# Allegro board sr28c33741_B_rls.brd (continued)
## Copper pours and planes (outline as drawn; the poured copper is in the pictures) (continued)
GND on TOP (solid shape): 53.28,38.06 48.51,38.06 48.25,38.01 48.02,37.86 45.55,35.39 45.4,35.16 45.35,34.9 45.35,32.22 45.4,31.96 45.55,31.73 48.07,29.21 48.3,29.06 48.56,29.01 51.29,29.01 51.78,28.91 52.21,28.62 58.19,22.64 58.42,22.49 58.68,22.44 60.44,22.44 60.94,22.64 61.14,23.14 61.14,28.14 61.09,28.41 60.94,28.64 59.27,30.3 58.99,30.72 58.89,31.22 58.89,33.86 58.8,34.07 58.59,34.16 58.49,34.16 58.07,34.33 57.89,34.76 57.89,37.37 57.69,37.86 57.19,38.06 53.29,38.06 53.29,38.72 57.19,38.72 58.15,38.32 58.54,37.37 58.54,34.8 58.59,34.8 59.26,34.53 59.54,33.86 59.54,31.22 59.59,30.97 59.73,30.76 61.4,29.1 61.69,28.66 61.79,28.14 61.79,23.14 61.4,22.18 60.44,21.79 58.68,21.79 58.17,21.89 57.73,22.18 51.75,28.16 51.54,28.31 51.29,28.36 48.56,28.36 48.05,28.46 47.61,28.75 45.09,31.27 44.8,31.71 44.7,32.22 44.7,34.9 44.8,35.41 45.09,35.85 47.56,38.32 48,38.61 48.51,38.72 53.28,38.72
GND on TOP: -0.19,70.45 -0.19,-0.36 69.68,-0.36 69.68,70.45 ; 2 cut-outs
GND on BOTTOM, LAYER_2, LAYER_3, LAYER_4, LAYER_5, LAYER_6, LAYER_7: -0.17,70.43 -0.17,-0.38 69.7,-0.38 69.7,70.43
GND_S2B on LAYER_2 (solid shape): 40.89,43.93 40.89,43.67 40.76,43.54 40.28,43.54 40.09,43.73 39.16,43.73 38.82,43.39 38.23,43.39 38.16,43.46 38.16,43.83 38.69,44.36 40.46,44.36
PGND_BOB on LAYER_2 (solid shape): 41.14,42.21 41.14,41.79 41.33,41.6 42.77,41.6 43.48,40.89 43.48,38.6 43.42,38.54 42.78,38.54 42.33,38.99 42.33,39.52 42,39.85 39.73,39.85 39.61,39.73 38.86,39.73 38.64,39.95 38.64,40.23 38.97,40.56 39.5,40.56 40.7,41.76 40.7,42.11 40.46,42.35 40.46,42.62 40.51,42.67 40.68,42.67
VDDCORE_CDC_1P2 on TOP (solid shape): 14.16,51.49 14.41,51.24 14.41,50.84 14.33,50.76 14.12,50.76 13.99,50.89 13.76,50.89 13.74,50.87 13.27,50.87 13.26,50.88 13.26,51.39 13.4,51.53 13.4,52.35 14.16,52.35
B_PLUS on TOP (solid shape): 40.86,34.81 41.04,34.63 41.52,34.63 41.52,34.13 40.19,34.13 39.91,34.41 39.91,36.59 40.86,36.59
B_PLUS on TOP (solid shape): 32.87,38.38 32.87,36.98 33.12,36.73 33.65,36.73 33.65,34.53 32.67,34.53 32.07,35.13 32.07,38.41 32.83,38.41
B_PLUS on TOP (solid shape): 13.03,23.34 12.57,23.34 12.23,23.67 12.23,24.27 12.11,24.39 11.88,24.39 11.78,24.49 11.78,24.67 11.87,24.76 13.03,24.76
B_PLUS on TOP (solid shape): 21.28,21.18 21.28,19.86 21.63,19.51 21.63,19.39 21.56,19.3 21.44,19.3 21.03,19.71 21.03,20.96 20.99,21 20.46,21 20.41,21.05 20.41,21.21 20.47,21.27 21.19,21.27
B_PLUS on TOP (solid shape): 59.08,50.34 59.08,50.11 59.26,49.93 59.77,49.93 59.77,49.4 59.83,49.33 59.83,48.6 59.38,48.6 59.38,49.08 59.03,49.43 58.69,49.43 58.54,49.58 58.54,50.53 58.64,50.63 58.79,50.63
B_PLUS on TOP (solid shape): 22.7,50.27 22.8,50.18 24,50.18 24.11,50.07 24.11,49.11 24.02,49.02 23.86,49.02 23.39,49.49 22.78,49.49 22.61,49.31 21.71,49.31 21.71,50.03 21.99,50.03 22.25,50.3 22.25,50.79 22.7,50.79
B_PLUS on TOP (solid shape): 34.84,43.4 35.03,43.4 35.37,43.06 35.37,42.96 35.34,42.94 35.17,42.77 35.09,42.72 35.04,42.66 34.97,42.66 34.54,43.09 33.79,43.09 33.79,43.54 34.7,43.54
B_PLUS on TOP (solid shape): 7.55,61.22 7.62,61.15 7.93,61.15 7.97,61.18 7.97,61.66 8.47,61.66 8.47,61.21 8.56,61.12 8.81,61.12 8.91,61.22 8.91,61.66 9.41,61.66 9.41,61.19 9.59,61.01 10.08,61.01 10.08,60.28 9.98,60.18 9.57,60.18 9.44,60.05 7.52,60.05 7.32,60.25 7.32,60.96 7.05,61.23 7.05,61.66 7.55,61.66
B_PLUS on TOP (solid shape): 24.8,19.31 24.8,18.88 24.39,18.48 23.17,18.48 23.05,18.6 22.95,18.62 22.88,18.62 22.87,18.62 22.81,18.68 22.81,18.77 22.88,18.84 22.94,18.84 22.98,18.85 23.5,18.85 23.57,18.93 24.1,18.93 24.25,19.07 24.25,19.31 24.3,19.36 24.75,19.36
B_PLUS on TOP (solid shape): 10.63,21.2 10.78,21.2 10.78,19.8 10.74,19.8 10.74,19.2 10.49,19.2 10.49,19.53 10.42,19.53 10.41,19.51 10.41,18.73 10.37,18.69 10.14,18.69 10.1,18.73 10.1,19.6 10.3,19.8 10.3,19.9 10.26,19.94 10.17,19.94 10.09,19.86 10.09,19.76 9.29,19.76 9.29,21.56 10.09,21.56 10.09,20.46 10.16,20.39 10.27,20.39 10.33,20.46 10.33,21.41 10.33,21.41 10.33,21.7 10.63,21.7
B_PLUS on TOP (solid shape): 22.73,55.85 22.88,55.74 23.06,55.77 23.26,55.56 23.95,55.56 23.95,55.12 23.48,55.12 23.24,54.87 22.88,54.87 22.83,54.92 22.83,55.06 22.9,55.13 22.91,55.23 22.9,55.35 22.89,55.35 22.58,55.66 22.58,55.78 22.61,55.81 22.65,55.85
B_PLUS on TOP (solid shape): 35.22,40.23 35.28,40.23 35.31,40.2 35.33,40.16 35.37,40.13 35.37,40.02 35.32,39.98 35.29,39.94 35.18,39.94 34.89,40.01 34.8,39.72 34.81,39.71 34.69,39.58 34.02,39.58 34.02,40.28 34.15,40.41 34.58,40.41 34.6,40.43 35.02,40.43
B_PLUS on TOP (solid shape): 36.69,44.35 36.69,43.98 36.84,43.83 36.84,43.72 37,43.56 37,43.41 37.07,43.34 37.07,43.18 37.04,43.15 36.92,43.15 36.85,43.22 36.76,43.25 36.75,43.25 36.71,43.3 36.71,43.31 36.64,43.44 36.51,43.5 36.5,43.5 36.46,43.55 36.46,43.56 36.39,43.68 36.27,43.75 36.26,43.75 36.08,43.93 36.08,44.5 36.54,44.5
B_PLUS on TOP (solid shape): 34.86,42.12 35,42.07 35.14,42.12 35.36,42.12 35.5,42.07 35.63,42.12 35.85,42.12 35.87,42.11 35.87,41.98 35.83,41.95 35.8,41.91 35.69,41.91 35.55,42.01 35.39,41.99 35.11,41.99 35,42.02 34.9,41.99 34.87,41.99 34.74,41.86 34.74,41.47 34.62,41.35 34.17,41.35 34.17,41.99 34.3,42.12
B_PLUS on TOP (solid shape): 22.84,56.77 23.05,56.77 23.13,56.85 23.28,56.85 23.41,56.72 23.78,56.72 23.92,56.58 23.92,56.07 23.47,56.07 23.47,56.35 23.47,56.36 23.22,56.61 23.1,56.61 22.93,56.69 22.76,56.6 22.53,56.38 22.37,56.38 22.33,56.42 22.33,56.46 22.34,56.47 22.44,56.57 22.48,56.71 22.48,56.72 22.6,56.81 22.64,56.87 22.65,56.88 22.73,56.88
B_PLUS on TOP (solid shape): 21.98,59.97 21.75,59.74 21.75,59.54 21.74,59.53 21.73,59.38 21.81,59.26 21.81,59.12 21.72,58.95 21.81,58.77 21.81,58.63 21.79,58.61 21.77,58.59 21.63,58.59 21.56,58.66 21.56,58.75 21.67,58.95 21.56,59.14 21.56,59.25 21.66,59.48 21.47,59.66 21.46,59.66 21.43,59.7 21.43,60.42 21.98,60.42
B_PLUS on TOP (solid shape): 40.09,41.8 39.72,41.43 39.72,40.88 39.58,40.74 39.33,40.74 39.21,40.78 39.08,40.74 38.84,40.74 38.66,40.77 38.52,40.67 38.52,40.66 38.45,40.66 38.34,40.77 38.34,40.85 38.42,40.93 38.53,40.93 38.55,40.9 38.75,40.84 38.91,40.96 39.01,40.96 39.37,40.9 39.3,41.26 39.3,41.35 39.43,41.51 39.36,41.71 39.8,42.14 40.09,42.14
B_PLUS on TOP (solid shape): 17.77,61.77 17.57,61.77 17.57,61 18.05,61 18.25,60.81 18.29,60.75 18.34,60.71 18.52,60.54 18.52,60.41 19.14,60.41 19.37,60.18 19.37,59.64 19.25,59.44 19.37,59.25 19.37,59.14 19.25,58.95 19.37,58.75 19.37,58.65 19.3,58.6 19.26,58.53 19.17,58.44 19.17,58.44 19.09,58.4 19.02,58.34 18.92,58.34 18.88,58.38 18.84,58.42 18.84,58.51 18.95,58.7 18.84,58.89 18.84,59 18.95,59.18 18.86,59.37 18.86,59.56 18.72,59.7 18.16,59.7 17.38,60.48 17.38,60.51 17.35,60.51 17.31,60.55 15.87,60.55 15.51,60.91 15.51,61.83 17.09,61.83 17.33,62.07 17.77,62.07
B_PLUS on LAYER_3 (solid shape): 24.82,21.65 24.82,19.26 24.73,19.17 24.3,19.17 23.79,19.68 23.79,21.46 23.29,21.96 23.29,22.14 23.34,22.19 24.28,22.19
B_PLUS on LAYER_3 (solid shape): 40.15,26.68 40.15,26.4 40.1,26.35 36.77,26.35 36.29,25.87 35.65,25.87 35.58,25.94 35.58,26.21 36.3,26.93 39.9,26.93
B_PLUS on LAYER_5 (solid shape): 42.03,37.83 42.03,37.13 41.11,36.21 41.11,27.15 40.32,26.36 39.76,26.36 39.76,37.16 40.5,37.9 41.96,37.9
B_PLUS on LAYER_5 (solid shape): outline of 393 points within 7.33,48.66 23.91,67.05
B_PLUS on LAYER_7 (solid shape): outline of 128 points within 5.94,17.15 64.87,55.51
BATT_NEG_CONN on LAYER_7 (solid shape): 15.45,63.23 15.1,62.88 13.53,62.88 13.3,62.65 13.3,61.77 13,61.47 11.89,61.47 11.83,61.53 11.83,62.9 13.69,64.76 13.69,67.77 15.45,67.77
BATT_PLUS on TOP (solid shape): 13.17,61.33 13.33,61.17 13.33,59.84 13.3,59.81 13.07,59.81 12.99,59.88 12.99,60.01 12.8,60.2 12.51,60.2 12.35,60.36 12.35,61.54 12.53,61.72 12.53,62.41 13.17,62.41
BATT_PLUS on TOP (solid shape): 20,61.65 20,59.68 19.9,59.65 19.74,59.44 19.9,59.23 19.92,59.23 19.92,59.16 19.9,59.16 19.74,58.95 19.9,58.74 19.92,58.73 19.92,58.7 19.81,58.61 19.77,58.55 19.61,58.4 19.57,58.37 19.54,58.33 19.43,58.33 19.39,58.38 19.34,58.42 19.34,58.49 19.45,58.6 19.45,59.55 19.46,59.56 19.46,60.22 19.28,60.4 19.28,61.11 19.22,61.17 19.22,61.74 19.26,61.78 19.87,61.78
BATT_PLUS on LAYER_5 (solid shape): 16.19,63.61 18.77,63.61 19.94,62.44 19.94,61.29 19.87,61.22 19.14,61.22 18.77,61.59 14.8,61.59 14.61,61.77 13.25,61.77 13.19,61.71 12.69,61.71 12.5,61.9 12.5,62.16 14.37,62.16 14.37,62.71 13.45,62.71 13.45,62.16 12.5,62.16 12.5,62.52 12.34,62.68 11.66,62.68 11.45,62.47 11.19,62.47 11.09,62.56 11.09,62.86 10.46,63.49 10.46,64.28 10.57,64.39 15.41,64.39
BATT_PLUS on LAYER_7 (solid shape): 13.34,64.9 11.83,63.39 11.1,63.39 10.63,62.92 9.16,62.92 9.08,62.84 9.08,62.64 9.15,62.57 10.7,62.57 11.18,63.05 11.45,63.05 11.52,62.98 11.52,62.24 10.31,61.03 7.6,61.03 7.43,61.2 7.43,63.63 7.91,64.11 8.68,64.11 9.2,64.63 10.3,64.63 10.3,64.59 10.31,64.55 10.32,64.52 10.35,64.49 10.38,64.47 10.41,64.45 10.45,64.44 10.66,64.44 10.7,64.45 10.73,64.47 10.76,64.49 10.79,64.52 10.8,64.55 10.81,64.59 10.81,64.63 10.8,64.67 10.79,64.7 10.76,64.73 10.73,64.75 10.7,64.77 10.66,64.78 10.45,64.78 10.41,64.77 10.38,64.75 10.35,64.73 10.32,64.7 10.31,64.67 10.3,64.63 9.2,64.63 10.15,65.58 11.95,65.58 11.95,66.12 11.06,66.12 11.06,65.58 10.15,65.58 10.29,65.72 10.29,66.15 10.65,66.51 11.91,66.51 11.98,66.58 11.98,67.88 13.34,67.88
BATT_PLUS_FLIP on TOP (solid shape): 28.58,64.79 27.75,64.79 27.75,67.49 28.58,67.49
BATT_PLUS_FLIP on LAYER_2 (solid shape): 28.49,65.54 27.73,65.54 27.73,67.33 28.49,67.33
BATT_PLUS_FLIP on LAYER_3 (solid shape): 26.94,67.35 27.14,67.34 27.16,67.33 27.16,67.31 27.16,67.27 27.16,67.23 27.16,67.2 27.18,67.16 27.2,67.13 27.22,67.11 27.25,67.09 27.29,67.08 27.33,67.07 27.36,67.08 27.4,67.09 27.43,67.11 27.45,67.13 27.47,67.16 27.49,67.2 27.49,67.23 27.49,67.27 27.49,67.31 27.49,67.33 27.51,67.34 27.53,67.35 28.38,67.35 28.47,67.26 28.47,65.75 27.95,65.23 25.04,65.23 23.13,63.32 19.42,63.32 19.02,63.72 19.02,63.97 21.39,66.34 26.68,66.34 26.68,66.3 26.69,66.27 26.71,66.24 26.74,66.21 26.77,66.19 26.8,66.18 26.84,66.17 26.87,66.17 26.91,66.18 26.94,66.2 26.97,66.22 26.99,66.25 27,66.29 27.01,66.32 27.01,66.36 27,66.39 26.99,66.43 26.97,66.46 26.94,66.48 26.91,66.5 26.87,66.51 26.84,66.51 26.8,66.5 26.77,66.49 26.74,66.47 26.71,66.44 26.69,66.41 26.68,66.38 26.68,66.34 21.39,66.34 22.83,67.78 26.51,67.78
BATT_PLUS_FLIP on LAYER_7 (solid shape): 19.74,63.57 19.74,61.9 18.37,60.53 13.93,60.53 13.54,60.92 13.54,62.56 13.62,62.64 15.17,62.64 16.56,64.03 19.28,64.03
CDC_GNDA on LAYER_2 (solid shape): 10.92,22.51 10.92,22.49 11.02,22.39 11.74,22.39 11.88,22.53 12.67,22.53 12.73,22.47 12.73,22.3 12.22,21.79 11.85,21.79 11.53,21.47 11.46,21.47 10.67,22.26 10.67,22.51 10.74,22.58 10.85,22.58
CDC_GNDP1 on LAYER_2 (solid shape): 11.62,24.58 11.62,24.48 11.31,24.17 11.31,23.35 11.07,23.11 10.29,23.11 9.71,22.53 8.25,22.53 8.22,22.56 8.22,23.34 10.57,23.34 10.57,23.3 10.58,23.27 10.6,23.24 10.63,23.21 10.66,23.19 10.69,23.18 10.73,23.17 10.76,23.17 10.8,23.18 10.83,23.2 10.86,23.22 10.88,23.25 10.89,23.29 10.9,23.32 10.9,23.36 10.89,23.39 10.88,23.43 10.86,23.46 10.83,23.48 10.8,23.5 10.76,23.51 10.73,23.51 10.69,23.5 10.66,23.49 10.63,23.47 10.6,23.44 10.58,23.41 10.57,23.38 10.57,23.34 8.22,23.34 8.22,23.76 10.61,23.76 10.61,23.72 10.62,23.69 10.64,23.66 10.67,23.63 10.7,23.61 10.73,23.6 10.77,23.59 10.8,23.59 10.84,23.6 10.87,23.62 10.9,23.64 10.92,23.67 10.93,23.71 10.94,23.74 10.94,23.78 10.93,23.81 10.92,23.85 10.9,23.88 10.87,23.9 10.84,23.92 10.8,23.93 10.77,23.93 10.73,23.92 10.7,23.91 10.67,23.89 10.64,23.86 10.62,23.83 10.61,23.8 10.61,23.76 8.22,23.76 8.22,25.68 8.68,26.14 10.06,26.14
D_VSW_S1 on TOP (solid shape): 34.79,42.71 34.85,42.63 34.93,42.58 35.01,42.49 35.02,42.48 35.06,42.39 35.14,42.32 35.17,42.28 35.14,42.24 35.1,42.21 34.06,42.21 33.93,42.08 31.77,42.08 31.77,42.94 34.57,42.94
D_VSW_S2 on TOP (solid shape): 41.85,42.75 41,42.75 41,43.85 40.92,43.93 39.49,43.93 39.43,43.87 39.43,43.58 39.01,43.16 38.89,43.16 38.86,43.2 38.82,43.23 38.8,43.27 38.82,43.31 38.88,43.71 38.49,43.62 38.47,43.6 38.44,43.62 38.44,43.67 39.4,44.63 41.85,44.63
D_VSW_S3 on TOP (solid shape): 39.95,44.74 39.36,44.74 38.39,43.77 38.16,43.77 38.14,43.75 38.04,43.68 37.98,43.57 37.94,43.57 37.92,43.64 37.9,43.7 37.9,43.88 37.96,43.95 38.01,43.95 38.01,44.56 38.16,44.71 38.16,45.59 39.95,45.59
D_VSW_S4 on TOP (solid shape): 37.19,44.73 37.33,44.59 37.33,43.89 37.4,43.82 37.4,43.51 37.32,43.46 37.26,43.39 37.22,43.36 37.17,43.39 37.13,43.44 37.08,43.48 37.08,43.6 36.92,43.76 36.92,43.87 36.77,44.03 36.77,44.41 36.58,44.6 35.56,44.6 35.39,44.77 35.39,45.57 37.19,45.57
D_VSW_S5 on TOP (solid shape): 35.14,44.18 35.24,44.08 35.24,43.89 35.43,43.89 35.56,43.75 35.58,43.72 35.56,43.69 35.51,43.49 35.62,43.33 35.62,43.24 35.57,43.2 35.53,43.14 35.49,43.12 35.44,43.14 35.4,43.19 35.34,43.23 35.2,43.37 35.2,43.38 35.09,43.48 34.95,43.49 34.88,43.48 34.42,43.94 34.42,44.33 34.03,44.71 33.34,44.71 33.34,45.56 35.14,45.56
DDR_VDDQ on TOP (solid shape): 41.95,47.01 41.95,45.02 41.77,44.84 41.41,44.84 41.41,47.09 41.87,47.09
DDR_VDDQ on LAYER_3 (solid shape): outline of 113 points within 46.12,47.29 55.99,61.74
DDR_VDDQ on LAYER_6 (solid shape): outline of 641 points within 34.61,45.9 41.96,55.87
DDR_VDDQ on LAYER_7 (solid shape): 48.75,57.07 48.75,56.38 43.46,56.38 43,55.92 41.93,55.92 41.47,55.46 41.47,55.21 41.83,54.85 46.48,54.85 47.31,54.02 47.81,54.02 48.71,53.12 48.71,52.55 48.63,52.47 46.35,52.47 45.24,53.58 44.68,53.58 44.62,53.52 42.73,53.52 42.47,53.78 42.01,53.78 41.8,53.99 39.46,53.99 38.79,54.66 38.79,55.79 38.88,55.88 40.34,55.88 41.74,57.28 42.55,57.28 43.1,57.83 47.99,57.83
G_VSW_S1 on TOP (solid shape): 25.72,58.01 24.85,58.01 24.75,57.91 23.61,57.91 23.51,57.81 22.93,57.81 22.84,57.9 22.84,58.03 22.87,58.06 23.27,58.06 23.59,58.38 24.69,58.38 24.87,58.56 24.87,59.81 25.72,59.81
G_VSW_S2 on TOP (solid shape): 26.38,60.06 25.45,60.06 25.32,59.93 23.43,59.93 23.26,59.76 23.26,59.38 23.02,59.15 23.01,59.15 22.86,59.15 22.74,59.05 22.7,59.03 22.65,59.05 22.62,59.11 22.57,59.15 22.57,59.24 22.67,59.39 22.64,59.57 22.64,59.58 22.64,59.83 23.54,60.73 25.44,60.73 25.53,60.82 25.53,61.75 26.38,61.75
G_VSW_S3 on TOP (solid shape): 23.72,61.03 22.37,59.69 22.37,59.67 22.25,59.6 22.2,59.47 22.2,59.46 22.18,59.43 22.17,59.43 22.06,59.39 21.98,59.31 21.91,59.31 21.84,59.38 21.84,59.64 22.08,59.88 22.08,61.09 22.87,61.88 22.87,62.66 23.72,62.66
G_VSW_S4 on TOP (solid shape): 22.7,54.9 22.74,54.88 22.82,54.8 22.93,54.77 23.2,54.77 23.33,54.64 23.33,53.73 23.35,53.71 23.59,53.71 23.9,53.4 23.9,52.59 22.1,52.59 22.1,53.39 22.86,53.39 22.92,53.45 22.92,54.41 22.58,54.41 22.49,54.5 22.49,54.74 22.51,54.76 22.59,54.8 22.65,54.88
G_VSW_S5 on TOP (solid shape): 23.39,56.32 23.39,55.99 23.41,55.97 24.57,55.97 25.69,54.85 26.32,54.85 26.53,54.64 26.53,52.55 25.73,52.55 25.73,53.3 25.34,53.69 25.26,53.69 24.1,54.85 24.1,55.61 24.05,55.66 23.3,55.66 23.13,55.83 23.14,55.85 23.1,56.15 22.8,56.17 22.79,56.17 22.73,56.11 22.65,56.11 22.58,56.18 22.58,56.3 22.6,56.32 22.81,56.53 23.18,56.53
G_VSW_S6 on TOP (solid shape): 25.68,55.96 24.88,55.96 24.88,57.32 24.76,57.42 24.11,57.42 23.17,57.42 22.94,57.19 22.82,57.19 22.73,57.1 22.66,57.1 22.58,57.18 22.58,57.26 22.65,57.34 22.68,57.44 22.68,57.45 22.69,57.47 22.7,57.47 22.86,57.54 22.93,57.69 22.93,57.7 22.95,57.72 23.54,57.72 23.58,57.76 25.68,57.76
HAPTIC_OUT_N on LAYER_3 (solid shape): 12.79,13.64 12.79,13.47 12.73,13.42 12.33,13.42 11.91,13.84 11.64,13.84 11.57,13.91 11.57,14.2 11.63,14.26 12.17,14.26
HAPTIC_OUT_N_F on TOP (solid shape): 8.92,5.93 8.73,5.08 8.62,4.44 7.87,4.58 7.99,5.22 8.1,6.08
HAPTIC_OUT_P on LAYER_3 (solid shape): 11.46,13.5 11.58,13.47 11.74,13.42 11.89,13.28 11.89,13.18 11.78,13.07 11.21,13.07 9.38,13.91 9.34,13.99 9.45,14.24 9.68,14.3
HAPTIC_OUT_P_F on TOP (solid shape): 9.6,9.61 9.53,9.55 9.39,8.61 8.75,8.64 8.55,8.68 8.71,9.69 9.14,10.08
LDC_PWRKEEY_COM on LAYER_2 (solid shape): 26.66,11.53 26.66,11.25 26.61,11.2 25.42,11.2 25.04,10.83 25.04,10.02 24.77,9.74 24.55,9.74 24.45,9.84 24.45,11.25 25.04,11.84 26.35,11.84
LDSP_L_DM on LAYER_7 (solid shape): 37.97,13.33 38.17,13.14 39.29,13.14 39.29,12.49 37.43,12.49 37.24,12.68 37.24,13.85 37.98,13.85
LDSP_P_DM on LAYER_7 (solid shape): 37.11,13.51 37.11,12.69 36.9,12.48 34.98,12.48 34.98,13.08 36.03,13.08 36.26,13.31 36.26,13.55 37.07,13.55
M4670_LDSP_L_POS on BOTTOM (solid shape): 35.76,11.3 35.76,8.31 35.26,8.31 35.26,10.97 35.19,11.04 34.19,11.04 34.19,11.65 35.41,11.65
M4671_LDSP_L_NEG on BOTTOM (solid shape): 40.08,11.04 39.08,11.04 39.02,10.97 39.02,8.31 38.52,8.31 38.52,11.3 38.86,11.65 40.08,11.65
NFC_VTX on LAYER_3 (solid shape): 63.34,51.92 61.89,50.47 61.06,50.47 61.06,51.23 62.05,52.22 62.05,55.41 62.64,55.41 62.64,55.21 62.64,55.17 62.66,55.14 62.68,55.11 62.71,55.09 62.75,55.07 62.78,55.06 62.82,55.06 62.86,55.07 62.89,55.09 62.92,55.11 62.95,55.14 62.96,55.17 62.97,55.21 62.97,55.43 62.96,55.47 62.95,55.5 62.92,55.53 62.89,55.55 62.86,55.57 62.82,55.58 62.78,55.58 62.75,55.57 62.71,55.55 62.68,55.53 62.66,55.5 62.64,55.47 62.64,55.43 62.64,55.41 62.05,55.41 62.05,56.1 62.63,56.68 63.34,56.68
NFC_VTX_GND on LAYER_2 (solid shape): 62.21,51.17 61.33,51.17 60.72,50.56 60.72,48.36 60.2,48.36 60.2,50.99 61.06,51.85 62.21,51.85
S1C_PGND on TOP (solid shape): 25.34,50.05 25.34,49.53 25.65,49.22 26.84,49.22 27.27,48.79 27.27,48.2 27.26,48.19 25.42,48.19 24.99,48.62 24.99,48.63 25.03,48.76 24.99,48.9 24.99,48.91 24.99,49.03 24.99,49.03 24.96,49.33 24.67,49.41 24.62,49.42 24.61,49.47 24.63,49.55 24.62,49.64 24.62,49.89 24.63,49.97 24.62,50.03 24.61,50.05 24.71,50.14 25.25,50.14
S1C_PGND on LAYER_2 (solid shape): 26.14,50.07 26.14,48.62 26.08,48.56 25.3,48.56 24.99,48.87 24.99,49.13 24.84,49.29 24.61,49.29 24.36,49.04 23.86,49.04 23.65,48.83 23.23,48.83 23.09,48.97 23.09,50.42 23.33,50.66 25.55,50.66
S2C_PGND on TOP (solid shape): 57.64,51.04 57.64,51.03 57.6,50.9 57.63,50.76 57.64,50.75 57.64,50.63 57.63,50.63 57.66,50.33 57.95,50.25 58,50.24 58.01,50.19 58,50.11 58.01,50.02 58.01,49.77 58,49.69 58,49.63 58.01,49.61 57.93,49.53 57.38,49.53 57.29,49.62 57.29,50.13 57.25,50.13 57.13,50.25 55.98,50.25 55.36,50.87 55.36,51.45 57.23,51.45
S2C_PGND on LAYER_2 (solid shape): 57.69,50.63 57.69,50.5 57.8,50.39 57.93,50.39 58.13,50.59 58.83,50.59 58.97,50.73 59.45,50.73 59.64,50.54 59.64,49.45 58.95,48.76 57.94,48.76 56.54,50.16 56.54,51 56.6,51.06 57.27,51.06
SPK_BOOST_L on TOP (solid shape): 9.84,26.21 9.84,25 10.07,24.78 10.32,24.78 10.47,24.63 10.47,23.28 10.37,23.18 10.17,23.18 10.02,23.03 10.02,22.56 9.88,22.42 9.26,22.42 9.26,25.39 9.25,25.41 9.25,26.29 9.77,26.29
UNNAMED_9_AW8690_I72_PVDD1 on LAYER_2 (solid shape): 8.28,18.81 8.28,17.9 8.22,17.84 7.33,17.84 7.21,17.72 7.21,17.55 7.58,17.18 8.23,17.18 8.28,17.13 8.28,16.4 8.22,16.34 7.22,16.34 6.69,15.81 6.45,15.81 6.32,15.95 6.32,17.92 7.27,18.87 8.22,18.87
UNNAMED_9_AW8690_I72_PVDD1 on LAYER_3 (solid shape): 8.28,18.81 8.28,17.9 8.22,17.84 7.33,17.84 7.21,17.72 7.21,17.55 7.58,17.18 8.23,17.18 8.28,17.13 8.28,16.4 8.22,16.34 7.22,16.34 6.69,15.81 6.46,15.81 6.32,15.95 6.32,17.92 7.27,18.87 8.22,18.87
UNNAMED_9_AW8690_I72_SW1 on TOP (solid shape): 8.69,19.85 8.8,19.74 8.8,18.79 8.78,18.77 8.5,18.77 8.5,19.06 7.89,19.67 7.89,21.56 8.69,21.56
UNNAMED_12_CAPACITOR_I67_B on LAYER_3 (solid shape): 18.95,61.5 18.95,61.18 18.85,61.07 18.85,60.52 18.95,60.41 18.95,59.33 18.76,59.14 18.62,59.14 18.37,59.4 18.37,59.4 18.27,59.5 18.27,60.09 18.39,60.21 18.39,61.47 18.47,61.55 18.91,61.55
UNNAMED_12_CAPACITOR_I88_A on TOP (solid shape): 17.72,60.01 17.72,59.43 17.69,59.43 17.5,59.21 17.66,58.97 17.66,58.96 17.72,58.91 17.72,58.91 17.76,58.87 17.76,58.86 17.97,58.71 18.19,58.83 18.25,58.83 18.62,58.46 18.48,58.32 18.43,58.32 18.39,58.36 18.23,58.42 18.07,58.35 17.92,58.35 17.84,58.43 17.42,58.43 16.98,58.87 16.98,59.5 16.85,59.63 15.36,59.63 15.26,59.73 14.72,59.73 14.72,60.17 15.25,60.17 15.51,60.43 17.29,60.43
UNNAMED_12_INDUCTOR_I19_B on LAYER_3 (solid shape): 10.43,59.97 10.43,59.4 10.05,59.02 9.16,59.02 9.07,59.11 9.07,59.39 9.7,60.02 10.38,60.02
UNNAMED_13_CAPACITOR_I12_B on TOP (solid shape): 21.64,17.38 21.64,17.25 21.59,17.2 21.59,17.2 21.45,17.06 21.45,16.45 21.15,16.45 21.15,16.7 21.11,16.7 21.1,16.7 21.1,16.55 21.08,16.53 19.27,16.53 18.93,16.87 18.93,17.45 21.57,17.45
UNNAMED_13_INDUCTOR_I40_A on LAYER_3 (solid shape): 24.29,18.88 25.26,18.88 25.87,18.27 25.87,18 25.64,17.77 24.55,17.77 23.27,19.05 22.53,19.05 22.5,19.08 22.5,19.26 22.79,19.55 23.62,19.55
UNNAMED_13_INDUCTOR_I40_B on LAYER_3 (solid shape): 23.8,18.23 23.8,17.65 23.73,17.58 23.57,17.58 23.1,18.05 23.1,18.36 22.95,18.51 22.79,18.51 22.64,18.66 22.56,18.66 22.51,18.72 22.51,18.79 22.55,18.83 23.2,18.83
UNNAMED_13_INDUCTOR_I41_A on TOP (solid shape): 20.94,19.76 20.94,19.67 21.42,19.19 21.93,19.19 21.99,19.13 21.99,19.03 21.92,18.96 20.94,18.96 20.83,19.07 19.03,19.07 19.03,19.87 20.83,19.87
UNNAMED_28_INDUCTOR_I23_A on TOP (solid shape): 39.15,38.32 39.29,38.32 39.43,38.18 41.21,38.18 41.31,38.08 42.22,38.08 42.45,37.85 43.4,37.85 43.4,36.9 41.01,36.9 40.94,36.97 40.94,37.65 40.86,37.73 39.26,37.73 38.69,38.3 38.69,38.42 38.59,38.52 38.59,38.63 38.66,38.7 38.77,38.7
UNNAMED_28_INDUCTOR_I29_A on TOP (solid shape): 37.89,38.07 38.1,38.07 38.62,37.55 38.62,36.83 38.91,36.54 38.91,34.41 37.97,34.41 37.97,36.6 38.05,36.68 38.05,37.25 37.69,37.61 37.69,38.16 37.71,38.18 37.78,38.18
UNNAMED_28_INDUCTOR_I42_A on TOP (solid shape): 36.82,38.15 36.82,37.53 35.77,36.48 35.77,34.68 35.62,34.53 34.65,34.53 34.65,36.76 34.82,36.93 35.47,36.93 36.72,38.18 36.79,38.18
USB_IN_MID on TOP (solid shape): 17.38,58.35 17.79,58.35 17.79,58.34 17.93,58.24 18.11,58.27 18.35,58.27 18.38,58.25 18.49,58.14 18.5,58.13 18.54,58.05 18.62,57.99 18.62,57.92 18.57,57.89 18.54,57.86 18.39,57.86 18.23,57.93 18.07,57.86 17.9,57.86 17.83,57.91 17.75,57.93 17.74,57.93 17.72,57.95 16.56,57.95 15.84,57.95 15.55,58.23 15.55,58.69 17.04,58.69
USB_PWR on TOP (solid shape): 16.06,38.59 16.75,38.59 16.75,38.28 16.7,38.23 16.51,38.23 16.5,38.22 16.5,38.16 16.51,38.15 16.69,38.15 16.75,38.09 16.75,37.79 15.8,37.79 15.58,38.01 14.3,38.01 14.16,38.15 14.16,38.27 14.24,38.35 14.8,38.35 14.92,38.47 14.92,38.59 15.08,38.75 15.9,38.75
USB_PWR on LAYER_5 (solid shape): outline of 124 points within 15.22,9.04 29.77,38.59
USB_VBUS_CONN on BOTTOM (solid shape): 32.29,10.27 32.29,10.24 32.05,10.01 32.12,9.94 32.36,10.17 32.57,9.96 32.32,9.71 32.47,9.56 32.71,9.8 32.93,9.59 32.69,9.35 32.75,9.29 33.13,9.29 33.4,9.02 33.4,8.75 33.07,8.75 33.07,8.65 33.41,8.65 33.41,8.35 33.07,8.35 33.07,8.24 33.24,8.24 33.24,6.96 33.2,6.92 32.74,6.92 32.69,6.97 32.69,7.13 32.67,7.15 30.94,7.15 30.94,8.07 30.66,8.35 30.66,10.07 30.57,10.16 30.57,10.61 31.95,10.61
USB_VBUS_CONN on LAYER_2 (solid shape): 36.36,8.07 36.36,6.07 35.89,5.59 35.17,5.59 34.79,5.97 34.79,6.96 35.05,7.22 35.05,7.76 34.79,8.02 34.36,8.02 34.09,7.75 34.09,6.71 33.52,6.14 33.52,5.9 33.23,5.61 32.65,5.61 32.32,5.94 32.32,8.15 32.69,8.52 35.92,8.52
USB_VBUS_CONN on LAYER_3 (solid shape): 36.37,8.07 36.37,6.07 35.91,5.61 35.15,5.61 34.79,5.97 34.79,6.96 35.02,7.19 35.02,7.79 34.79,8.02 34.36,8.02 34.09,7.75 34.09,6.67 33.62,6.2 33.62,6 33.23,5.61 32.65,5.61 32.32,5.94 32.32,8.15 32.69,8.52 35.92,8.52
USB_VBUS_IN on TOP (solid shape): 16.32,39.38 16.32,39.12 16.34,39.09 16.39,39.09 16.39,39.34 16.69,39.34 16.69,39.31 16.74,39.25 16.74,39.08 16.76,39.07 16.88,39.07 16.89,39.08 16.89,39.34 17.21,39.34 17.25,39.3 17.25,39.11 17.27,39.09 17.3,39.09 17.35,39.14 17.35,39.37 17.41,39.44 17.92,39.44 17.92,38.88 17.84,38.8 17.36,38.8 17.24,38.68 16.13,38.68 15.96,38.85 15.44,38.85 15.3,38.99 15.3,39.12 15.17,39.25 15.03,39.25 14.94,39.34 14.94,39.47 15.03,39.56 16.14,39.56
USB_VBUS_IN on TOP (solid shape): 17.68,57.87 17.71,57.85 17.76,57.8 17.83,57.8 17.98,57.74 18.14,57.8 18.32,57.8 18.36,57.77 18.41,57.75 18.49,57.67 18.49,57.66 18.54,57.56 18.62,57.5 18.62,57.4 18.57,57.37 18.53,57.32 18.42,57.32 18.23,57.43 18.04,57.32 17.93,57.32 17.82,57.42 17.66,57.42 17.62,57.42 17.39,57.19 16.38,57.19 16.38,57.87 17.22,57.87
USB_VBUS_IN on LAYER_5 (solid shape): outline of 184 points within 15.31,38.89 17.62,57.6
VDISP_M_OUT on TOP (solid shape): 38.53,38.46 38.56,38.42 38.6,38.39 38.6,38.26 39.3,37.57 39.3,36.92 38.72,36.92 38.72,37.56 38.29,38 38.29,38.34 38.38,38.42 38.41,38.46
VDISP_M_OUT on LAYER_5 (solid shape): 52.66,67.82 52.51,67.82 51.94,67.25 51.94,65.53 51.62,65.21 51.62,64.84 51.88,64.57 51.88,63 51.8,62.92 51.61,62.92 51.19,63.35 51.19,67.22 52.01,68.04 52.66,68.04
VDISP_P_MID on TOP (solid shape): 37.6,37.57 37.95,37.23 37.95,36.76 37.77,36.58 37.77,36.05 37.6,35.89 36.92,35.89 36.92,36.54 37.37,36.99 37.37,37.78 37.6,37.78
VDISP_P_OUT on TOP (solid shape): 37.25,37.04 36.45,36.25 36.46,36.25 36.46,36.05 36.46,36.05 35.96,36.05 35.96,36.55 36.9,37.49 36.9,37.93 37.08,38.11 37.25,38.11
VDISP_P_OUT on LAYER_5 (solid shape): 51.38,67.85 51.01,67.48 51.01,63.41 51.22,63.19 51.22,63.07 51.11,62.96 50.81,62.96 50.44,63.33 50.44,68.07 51.38,68.07
VPA_APT on TOP (solid shape): 21.28,18.18 21.28,17.93 21.42,17.79 22.97,17.79 23.03,17.73 23.03,17.61 22.99,17.57 20.92,17.57 20.82,17.67 19.03,17.67 19.03,18.47 20.99,18.47
VPA_APT on TOP (solid shape): 51.56,24 51.51,23.94 51.51,23.74 51.39,23.62 51.39,23.12 51.37,23.1 51.08,23.1 51.08,23.63 50.97,23.74 50.97,23.89 51.31,24.23 51.31,24.57 51.3,24.58 50.98,24.58 50.92,24.64 50.92,24.89 50.98,24.95 51.56,24.95
VPA_APT on LAYER_7 (solid shape): 51.55,24.84 51.55,22.54 48.58,19.57 40.77,19.57 39.33,21 39.34,21.01 38.93,21.42 38.23,21.42 37.89,21.08 30.62,21.08 28.97,19.43 22.07,19.43 21.58,18.94 21.58,18.63 21.81,18.4 22.03,18.4 22.26,18.17 22.26,17.56 22.1,17.4 20.92,17.4 20.33,17.99 20.33,19.91 22.09,21.67 28.43,21.67 30.09,23.33 31.92,23.33 32.03,23.44 32.56,23.44 32.61,23.38 43.31,23.38 43.77,22.92 48.33,22.92 50.37,24.96 51.43,24.96
VPA_APT_GSM on TOP (solid shape): 23.42,17.4 23.42,16.52 23.26,16.36 22.66,16.36 22.66,16.95 22.47,17.14 22.47,17.41 22.52,17.46 23.04,17.46 23.12,17.54 23.28,17.54
VPA_APT_GSM on TOP (solid shape): 52.27,16.45 52.02,16.45 52.02,16.62 51.86,16.78 51.23,16.78 51.16,16.85 51.16,17.23 51.22,17.29 51.67,17.29 52,16.95 52.02,16.95 52.02,17.26 51.9,17.38 51.78,17.38 51.52,17.64 51.52,18.2 52.27,18.2
VPA_APT_GSM on LAYER_3 (solid shape): 21.98,18.36 21.98,18.01 22.33,17.66 23.16,17.66 23.41,17.41 23.41,17.22 23.22,17.03 22.35,17.03 21.64,17.75 21.64,18.25 21.81,18.42 21.92,18.42
VPA_APT_GSM on LAYER_7 (solid shape): 40.39,18.53 50.99,18.53 51.71,17.81 51.71,17.08 51.53,16.9 40.31,16.9 39.58,17.63 30.68,17.63 30.26,17.21 23.12,17.21 23.01,17.32 23.01,18.16 23.38,18.53 29.44,18.53 29.94,19.03 39.89,19.03
VREG_BOB on TOP (solid shape): 40.05,42.51 39.9,42.35 39.6,42.35 39.6,42.13 39.32,41.85 39.18,41.85 39.17,41.86 39.14,41.92 39.09,41.97 39.07,41.99 39.07,42.09 39.14,42.17 39.18,42.26 39.18,42.27 39.24,42.32 39.25,42.32 39.4,42.43 39.41,42.62 39.34,42.81 39.56,43.02 40.05,43.02
VREG_BOB on TOP (solid shape): 41.53,39.1 41.73,39.1 42.03,38.8 42.03,38.19 41.32,38.19 41,38.51 41,38.85 40.9,38.95 39.54,38.95 39.43,39.06 39.43,39.07 39.27,39.28 39.02,39.19 38.9,39.19 38.71,39.29 38.53,39.19 38.43,39.19 38.39,39.24 38.34,39.28 38.34,39.36 38.38,39.39 38.42,39.44 38.53,39.44 38.61,39.36 38.71,39.35 38.78,39.36 39.14,39.36 39.21,39.35 39.28,39.36 39.45,39.36 39.63,39.54 41.09,39.54
VREG_BOB on LAYER_5 (solid shape): 22.04,56.88 22.04,56.47 22.01,56.44 21.91,56.44 21.86,56.49 21.62,56.49 21.45,56.67 21.45,56.79 21.29,56.95 20.16,56.95 19.97,57.14 19.97,57.27 20.05,57.35 21.56,57.35
VREG_BOB on LAYER_5 (solid shape): 40.97,44.8 40.97,42.72 40.97,42.28 41.93,41.32 41.93,38.65 41.84,38.56 41.28,38.56 39.64,40.2 37.96,40.2 37.88,40.28 37.88,40.4 38.22,40.74 39.22,40.74 39.43,40.95 39.43,41.71 39.29,41.85 39.62,41.85 39.62,41.81 39.63,41.77 39.65,41.74 39.67,41.71 39.7,41.69 39.73,41.67 39.77,41.66 39.79,41.66 40.03,41.66 40.03,41.66 40.16,41.66 40.2,41.67 40.23,41.69 40.26,41.71 40.28,41.74 40.3,41.78 40.31,41.81 40.31,41.85 40.3,41.89 40.28,41.92 40.26,41.95 40.23,41.97 40.2,41.99 40.16,42 40.14,42 39.9,42 39.89,42 39.77,42 39.73,41.99 39.7,41.97 39.67,41.95 39.65,41.92 39.63,41.89 39.62,41.85 39.29,41.85 39.22,41.92 38.78,41.92 38.63,42.07 38.63,42.5 38.77,42.64 39.43,42.64 40.05,43.26 40.05,44.85 40.11,44.91 40.86,44.91
VREG_BOB on LAYER_5 (solid shape): outline of 129 points within 17.01,45.11 18.87,56.12
VREG_BOB on LAYER_7 (solid shape): 20.16,57.18 20.16,56.93 18.8,55.57 17.88,55.57 17.82,55.63 17.82,55.79 19.3,57.27 20.07,57.27
VREG_BOB on LAYER_7 (solid shape): 32.58,44.83 39.35,44.83 39.67,45.15 40.78,45.15 40.97,44.96 40.97,44.4 40.82,44.25 40.07,44.25 39.88,44.44 39.42,44.44 39.01,44.03 38.1,44.03 37.94,44.19 36.46,44.19 36.3,44.03 36.3,43.6 36.81,43.09 36.81,43.03 36.73,42.95 35.42,42.95 34.86,43.51 31.36,43.51 30.37,44.5 18.21,44.5 17.57,45.14 17.57,45.68 18.14,46.25 31.16,46.25
VREG_L1B_0P88 on LAYER_7 (solid shape): 34.1,51.38 34.23,51.25 34.23,50.68 33.88,50.33 30.02,50.33 29.55,50.79 28.06,50.79 28.06,50.96 28.44,51.34 28.62,51.34 28.81,51.15 29.78,51.15 29.93,51 31.44,51 31.71,50.73 32.76,50.73 33.41,51.38
VREG_L1B_0P88 on LAYER_7 (solid shape): 38.04,51.65 38.04,51.15 37.56,50.67 37.17,50.67 37.06,50.56 37.06,50.38 37.16,50.27 37.8,50.27 37.94,50.14 37.94,49.33 37.32,48.71 37.28,48.71 36.4,49.59 36.4,50.07 36.59,50.27 36.76,50.27 36.88,50.38 36.88,50.75 36.99,50.86 37.23,50.86 37.34,50.97 37.34,51.21 37.21,51.34 37.21,51.54 37.49,51.82 37.87,51.82
VREG_L3A_1P0_SDR_DVDD on LAYER_3 (solid shape): 23.68,37.99 23.88,37.99 23.99,37.88 23.99,37.79 23.93,37.73 23.04,37.73 22.94,37.83 19.57,37.83 19.43,37.97 19.43,38.2 19.57,38.33 23.34,38.33
VREG_L3B_3P0 on LAYER_5 (solid shape): 37.77,45.84 37.77,45.24 37.4,44.87 37.4,43.41 37.29,43.3 37.29,43.18 37.02,42.92 36.99,42.92 36.96,42.91 36.93,42.89 36.9,42.87 36.87,42.84 36.86,42.81 36.85,42.77 36.85,42.74 36.81,42.7 36.43,42.7 36.4,42.73 36.4,42.88 36.41,42.9 36.43,42.93 36.44,42.96 36.44,42.99 36.44,43.03 36.43,43.07 36.53,43.07 36.53,43.03 36.54,43 36.56,42.97 36.59,42.94 36.62,42.92 36.65,42.91 36.69,42.9 36.72,42.9 36.76,42.91 36.79,42.93 36.82,42.95 36.84,42.98 36.85,43.02 36.86,43.05 36.86,43.09 36.85,43.12 36.84,43.16 36.82,43.19 36.79,43.21 36.76,43.23 36.72,43.24 36.69,43.24 36.65,43.23 36.62,43.22 36.59,43.2 36.56,43.17 36.54,43.14 36.53,43.11 36.53,43.07 36.43,43.07 36.37,43.15 36.81,43.58 36.81,43.64 36.85,43.67 36.87,43.69 36.89,43.72 36.91,43.75 36.91,43.78 36.91,43.82 36.91,43.85 36.89,43.89 36.87,43.91 36.85,43.94 36.81,43.96 36.81,45.27 37.44,45.9 37.71,45.9
VREG_L4B_2P95 on LAYER_2 (solid shape): 55.19,55.76 55.19,54.52 55.1,54.44 54.67,54.44 54.07,53.84 52.65,53.84 52.53,53.96 52.53,55.04 52.59,55.1 52.9,55.1 52.91,55.1 53.47,55.1 54.36,55.99 54.96,55.99
VREG_L4B_2P95 on LAYER_5 (solid shape): 44.16,40.36 43.7,40.36 43.7,43.87 44.16,43.87
VREG_L5A_0P8 on LAYER_7 (solid shape): 38.25,59.78 38.25,57.95 38.18,57.88 37.73,57.88 37.41,58.2 37.41,58.69 37.03,59.07 36.43,59.07 36.36,59 33.44,59 33.4,58.97 33.36,58.95 33.32,58.98 33.27,59.04 33.21,59.06 33.17,59.08 33.16,59.12 33,59.3 32.83,59.12 32.83,59.11 32.72,59 32.07,59 31.91,59.16 31.68,59.16 31.46,58.94 29.09,58.94 29.09,58.94 27,56.85 21.87,56.85 21.39,56.37 21.39,55.84 20.71,55.16 20.71,54.7 20.77,54.64 20.77,54.23 20.7,54.16 20.57,54.16 20.24,54.49 20.24,56.03 22.6,58.39 26.67,58.39 28.32,60.04 35.72,60.04 36.38,60.7 37.33,60.7
VREG_L6A_1P3 on LAYER_5 (solid shape): 58.27,37.12 58.27,34.56 57.52,33.81 57.04,33.81 56.92,33.92 56.92,34.81 57.42,35.31 57.42,36.55 57.24,36.73 56.9,36.73 56.11,37.52 55.26,37.52 54.97,37.81 54.97,37.96 55.31,38.3 57.09,38.3
VREG_L6A_1P3 on LAYER_7 (solid shape): 50.61,36.38 50.61,34.16 51.24,33.52 51.8,33.52 52.14,33.86 52.33,33.86 52.53,33.66 54.84,33.66 56.1,34.92 57.1,34.92 57.16,34.86 57.16,33.9 55.83,32.57 49.98,32.57 49.5,33.05 49.5,35.43 49.25,35.68 49.25,36.34 49.81,36.9 50.09,36.9
VREG_L7A_1P2_RF on LAYER_3 (solid shape): 25.96,36.63 25.96,36.46 25.87,36.37 22.48,36.37 22.44,36.41 22.44,36.53 22.65,36.74 25.85,36.74
VREG_L7A_1P2_RF on LAYER_7 (solid shape): 22.8,36.69 22.8,36.47 22.71,36.38 20.14,36.38 20.03,36.49 20.03,36.68 20.13,36.79 22.7,36.79
VREG_L7B_3P125 on LAYER_3 (solid shape): 34.74,51.19 34.74,50.75 34.41,50.43 34.4,50.45 34.23,50.48 34.12,50.36 34.12,50.35 33.86,50.09 33.71,50.09 33.65,50.03 33.49,50.03 33.04,49.58 32.91,49.58 32.72,49.4 32.25,48.92 31.81,48.92 31.62,48.73 31.1,48.73 31.01,48.64 30.64,48.64 30.49,48.79 30.49,49.23 30.81,49.56 31.49,49.56 31.54,49.5 32,49.5 32.55,50.05 32.9,50.4 33.09,50.4 33.19,50.36 33.29,50.4 33.3,50.4 33.33,50.4 33.83,50.9 34.03,50.9 34.04,50.92 34.09,50.93 34.13,50.91 34.4,50.87 34.32,51.14 34.31,51.14 34.29,51.17 34.32,51.19 34.32,51.25 34.43,51.36 34.57,51.36
VREG_L8A_1P8 on LAYER_2 (solid shape): 55.17,58.48 55.17,57.93 55.03,57.79 54.61,57.79 53.22,56.4 52.04,56.4 52.04,56.58 52.53,57.07 52.53,57.49 53.6,58.56 55.09,58.56
VREG_L8A_1P8 on LAYER_2 (solid shape): 55.19,54.02 55.19,53.36 54.63,52.83 54.51,52.82 51.51,52.82 50.99,53.35 50.99,53.57 51.06,53.64 51.22,53.64 51.42,53.44 54.24,53.44 54.93,54.12 55.08,54.12
VREG_L8B_3P3 on LAYER_3 (solid shape): 50.87,35.45 50.87,34.68 50.46,34.27 50.14,34.27 49.82,34.59 49.82,35 50.34,35.52 50.8,35.52
VREG_L8B_3P3 on LAYER_5 (solid shape): outline of 96 points within 45.5,32.49 50.45,35.79
VREG_L9B_0P8 on LAYER_5 (solid shape): 38.94,46.26 38.94,43.11 38.53,42.7 38.42,42.7 38.39,42.73 38.39,45.98 38.76,46.35 38.85,46.35
VREG_L9B_0P8 on LAYER_5 (solid shape): 35.52,51.8 35.52,51.62 35.29,51.39 35.29,49.71 34.41,48.83 34.34,48.79 34.27,48.7 34.28,48.69 34.28,48.26 33.83,47.81 33.26,47.81 32.9,48.17 32.9,48.59 33.19,48.88 33.19,49.28 33.82,49.91 33.82,50.82 34.29,51.29 34.29,51.55 34.37,51.63 34.38,51.62 34.51,51.58 34.62,51.65 34.65,51.71 34.65,51.79 34.66,51.83 34.7,51.85 35.47,51.85
VREG_L9B_0P8 on LAYER_7 (solid shape): 35.08,47.69 35.08,46.91 35.78,46.21 37.05,46.21 37.33,46.49 38.73,46.49 38.89,46.33 38.89,46.22 38.71,46.04 37.46,46.04 37.2,45.78 33.95,45.78 32.66,47.07 32.66,48.41 32.87,48.62 32.87,48.88 32.95,48.97 33.8,48.97
VREG_L10B_0P8 on LAYER_5 (solid shape): 34.78,52.14 34.78,51.98 34.73,51.93 34.56,51.93 34.54,51.91 34.52,51.91 34.37,51.87 34.32,51.71 34.32,51.7 34.21,51.58 34.21,51.44 34.18,51.4 34.13,51.4 33.89,51.37 33.93,51.13 33.95,51.09 33.94,51.05 33.73,50.84 33.73,49.96 33.09,49.32 33.09,48.93 32.88,48.72 32.46,48.72 32.34,48.84 32.34,49.35 32.89,49.9 32.89,50.35 32.98,50.44 32.98,50.86 32.91,50.93 32.91,51.19 33.12,51.4 33.36,51.4 34.06,52.1 34.07,52.11 34.15,52.15 34.2,52.24 34.2,52.25 34.31,52.35 34.57,52.35
VREG_L13A_1P8 on TOP (solid shape): outline of 340 points within 51.44,48.26 54.5,62.54
VREG_L13A_1P8 on LAYER_7 (solid shape): 54.22,49.34 54.22,48.98 53.42,48.18 46.68,48.18 46.3,47.8 46.22,47.8 46.18,47.84 46.18,48.26 46.04,48.4 45.18,48.4 44.76,47.98 42.41,47.98 42.38,48.01 42.38,48.76 42.69,49.08 42.69,49.4 42.75,49.45 43.03,49.45 43.1,49.38 51.2,49.38 51.42,49.6 53.96,49.6
VREG_L19A_3P3 on TOP (solid shape): 58.08,30.09 58.12,30.05 58.95,30.05 58.95,29.59 58.34,29.59 58.08,29.85 58.02,29.85 57.99,29.82 57.99,29.58 57.69,29.58 57.69,29.82 57.59,29.92 57.02,29.92 57.01,29.91 57.01,30.17 57.78,30.17 57.78,30.25 58.08,30.25
VREG_L19A_3P3 on LAYER_7 (solid shape): 58.86,35.59 58.86,29.66 58.71,29.51 55.28,29.51 54.71,30.08 54.71,30.42 54.84,30.55 56.84,30.55 56.96,30.67 56.96,33.17 57.39,33.6 57.39,34.99 57.22,35.16 56.14,35.16 54.95,36.36 54.95,37.6 54.77,37.78 54.6,37.78 53.44,38.95 53.44,39.54 54.91,39.54
VREG_OLEDB on TOP (solid shape): 36.5,38.5 36.54,38.47 36.57,38.43 36.6,38.4 36.6,38.19 35.45,37.04 32.99,37.04 32.99,37.48 34.27,37.48 34.69,37.9 35.09,37.9 35.27,38.08 36.05,38.08 36.15,38.18 36.32,38.35 36.4,38.4 36.45,38.47
VREG_S1A_0P752 on TOP (solid shape): 27.45,59.79 27.45,59.23 27.48,59.2 27.78,59.2 27.78,58.95 27.36,58.95 27.25,58.83 27.25,58.01 26.42,58.01 26.42,59.81 26.88,59.81 26.91,59.84 27.4,59.84
VREG_S1A_0P752 on TOP (solid shape): 34.94,62.66 35.33,62.66 35.33,62.36 35.08,62.36 35.05,62.33 35.05,62.28 35.17,62.16 35.17,61.51 35.02,61.36 34.94,61.36 34.89,61.31 34.88,61.31 34.79,61.21 34.79,61.1 34.69,61 33.95,61 33.82,60.87 33.82,60.59 33.81,60.58 33.55,60.58 33.55,60.89 33.46,60.97 33.45,60.99 32.97,60.99 32.89,60.91 32.89,60.58 32.64,60.58 32.64,60.93 32.48,61.09 31.18,61.09 30.89,61.38 30.89,61.51 34.96,61.51 34.96,62.31 31.02,62.31 31.02,61.51 30.89,61.51 30.89,62.53 31.14,62.78 34.82,62.78
VREG_S1A_0P752 on LAYER_5 (solid shape): outline of 500 points within 26.88,55.42 36.05,62.72
VREG_S1B_0P752 on TOP (solid shape): 32.71,47.38 32.32,47.38 32.32,47.17 32.69,47.17 32.69,44.9 33.12,44.46 33.56,44.46 33.56,43.61 31.75,43.61 31.75,44.5 31.62,44.64 31.62,46.09 31.19,47.04 31.19,47.6 32.26,47.6 32.29,47.63 32.71,47.63
VREG_S1B_0P752 on LAYER_6 (solid shape): outline of 1388 points within 30.16,47.05 42.23,62.31
VREG_S1C_1P125 on TOP (solid shape): 27.01,51.8 27.01,51.48 27.27,51.23 27.27,49.6 25.44,49.6 25.44,50.38 25.76,50.7 25.76,52.23 26.59,52.23
VREG_S1C_1P125 on LAYER_3 (solid shape): 27.44,49.73 27.44,49.57 27.43,49.56 28.05,48.95 28.05,48.68 27.98,48.61 27.83,48.61 27.02,49.42 27.02,49.84 27.14,49.96 27.21,49.96
VREG_S2A_S3A_0P752 on TOP (solid shape): 29.6,60.8 30.07,60.8 30.07,60.56 29.88,60.56 29.86,60.54 29.86,60.51 30.14,60.23 30.14,56.86 30.63,56.86 30.63,56.61 30.13,56.61 30.13,55.48 30.59,55.48 30.6,55.46 30.63,55.42 30.67,55.38 30.69,55.37 30.69,55.21 28.65,55.21 28.46,55.4 28.46,56.62 28.85,56.62 28.85,55.32 29.65,55.32 29.65,56.62 29.66,56.62 29.66,60.52 28.86,60.52 28.86,56.62 28.46,56.62 28.46,58.98 27.38,60.06 27.08,60.06 26.89,60.25 26.89,61.55 26.47,61.97 25.27,61.97 25.27,60.86 24.42,60.86 24.42,62.66 27.74,62.66
VREG_S2A_S3A_0P752 on LAYER_3 (solid shape): outline of 1633 points within 24.83,54.57 34.36,61.74
VREG_S2B_0P752 on TOP (solid shape): 39.26,48.67 39.01,48.67 39.01,48.59 39.03,48.57 39.41,48.57 39.41,47.4 38.48,47.4 38.48,48.57 38.8,48.57 38.81,48.58 38.81,48.66 38.79,48.68 38.54,48.68 38.53,48.67 38.53,48.97 39.26,48.97
VREG_S2B_0P752 on TOP (solid shape): 40.88,48.86 41.93,48.86 43.4,47.39 43.4,42.75 42.55,42.75 42.55,44.6 42.21,44.94 42.21,47.08 41.85,47.44 40.31,47.44 40.31,47.97 41.84,47.97 41.84,48.53 40.79,48.53 40.79,47.97 40.31,47.97 40.31,48.54 40.69,48.54 40.69,48.66 40.39,48.66 40.39,48.96 40.78,48.96
VREG_S2B_0P752 on LAYER_3 (solid shape): outline of 435 points within 36.22,51.37 39.24,53.62
VREG_S2B_0P752 on LAYER_5 (solid shape): outline of 625 points within 36.75,47.39 42.17,53.58
VREG_S2C_1P125 on TOP (solid shape): outline of 155 points within 46.46,46.83 57.19,61.86
VREG_S2C_1P125 on LAYER_7 (solid shape): 55.12,52.8 55.12,52.68 55.09,52.65 55.09,52.18 55.1,52.16 55.1,51.86 55.07,51.83 55.07,50.43 54.47,49.83 50.29,49.83 50.1,50.02 50.1,50.28 50.59,50.77 52.49,50.77 54.56,52.84 55.08,52.84
VREG_S3B_S4B_0P752 on TOP (solid shape): 35.45,48.74 35.96,48.74 36.12,48.58 36.91,48.58 36.99,48.5 36.99,47.52 37.24,47.27 39.42,47.27 39.42,47.14 39.96,47.14 39.96,46.29 38.16,46.29 38.16,46.77 36.56,46.77 36.56,46.29 35.39,46.29 35.39,47.21 33.78,47.21 33.78,48.11 33.88,48.11 33.88,48.53 33.93,48.53 33.93,47.73 35.23,47.73 35.23,48.52 35.79,48.52 35.79,47.22 36.59,47.22 36.59,48.52 36.39,48.52 35.23,48.52 35.23,48.53 34.67,48.53 34.64,48.54 34.62,48.55 34.62,48.57 34.63,48.62 34.64,48.65 34.63,48.69 34.63,48.73 34.61,48.76 34.58,48.79 34.56,48.82 34.52,48.83 34.48,48.84 34.45,48.84 34.41,48.83 34.38,48.82 34.35,48.79 34.32,48.76 34.31,48.73 34.3,48.69 34.3,48.65 34.3,48.62 34.31,48.57 34.31,48.55 34.29,48.54 34.26,48.53 33.88,48.53 33.88,48.86 34.06,49.04 35.15,49.04
VREG_S3B_S4B_0P752 on LAYER_5 (solid shape): outline of 1990 points within 34.03,46.24 40.43,62.66
VREG_S4A_2P04 on TOP (solid shape): 19.82,54.77 19.82,53.66 20.01,53.47 20.01,52.29 20.19,52.11 23.69,52.11 23.81,51.99 23.9,51.99 23.9,51.19 22.08,51.19 21.95,51.32 19.97,51.32 19.71,51.58 19.44,51.58 19.44,51.88 19.69,51.88 19.71,51.9 19.71,51.93 19.69,51.95 19.51,51.95 19.51,54.31 19.61,54.41 19.61,54.78 19.65,54.82 19.77,54.82
VREG_S5A_0P752 on TOP (solid shape): 30.27,54.07 30.27,53.62 30.68,53.62 30.68,53.35 30.38,53.35 30.24,53.21 30.24,52.76 30.32,52.68 30.68,52.68 30.68,52.4 30.44,52.4 30.39,52.35 30.39,52.25 30.44,52.2 30.68,52.2 30.68,51.95 30.67,51.95 30.3,51.95 30.23,52.01 29.77,52.01 29.77,51.94 28.56,51.94 28.25,52.25 27.83,52.25 27.61,52.47 27.21,52.47 27.13,52.55 27.13,54.35 28.83,54.35 28.83,52.01 29.66,52.01 29.72,52.07 29.72,54.45 29.89,54.45
VREG_S5A_0P752 on LAYER_5 (solid shape): outline of 417 points within 28.51,51.16 34.61,55.16
VREG_S6A_1P35 on TOP (solid shape): 27.08,56.59 27.17,56.5 27.98,56.5 27.98,56.05 27.2,56.05 27.18,56.02 27.18,56.01 27.08,55.91 27.08,55.65 26.91,55.48 26.91,55.01 26.46,55.01 26.46,55.58 26.28,55.76 26.28,57.5 27.08,57.5
VREG_S6A_1P35 on LAYER_7 (solid shape): 26.88,55.82 26.88,55.57 26.21,54.9 20.95,54.9 20.95,55.09 21.58,55.72 26.26,55.72 26.4,55.86 26.84,55.86
VSW_BCK_BOB on TOP (solid shape): 43.35,40.76 43.12,40.53 41.2,40.53 41.2,41.16 40.3,41.16 40.3,40.63 39.9,40.23 39.38,40.23 39.19,40.3 39.01,40.19 38.92,40.19 38.87,40.24 38.81,40.28 38.58,40.52 38.58,40.59 38.64,40.65 38.81,40.65 38.96,40.59 39.12,40.65 39.62,40.65 39.8,40.83 39.8,41.39 40.02,41.61 43.35,41.61
VSW_BST_BOB on TOP (solid shape): 41.19,40.38 43.05,40.38 43.35,40.08 43.35,39.21 41.55,39.21 41.17,39.6 41.17,39.72 40.33,39.72 40.33,39.64 39.61,39.64 39.54,39.57 39.54,39.57 39.45,39.48 39.11,39.48 38.96,39.54 38.81,39.48 38.63,39.48 38.58,39.53 38.58,39.62 38.61,39.65 38.63,39.67 38.66,39.72 38.78,39.83 38.86,39.87 38.92,39.93 39.01,39.93 39.2,39.82 39.4,39.92 39.44,39.94 39.46,39.97 39.49,40.02 39.49,40.08 39.51,40.11 39.54,40.13 39.92,40.13 40.17,40.38

Small or netless copper shapes (teardrops, artwork), in the pictures only: 39 on TOP, 5 on BOTTOM, 25 on LAYER_2, 40 on LAYER_3, 27 on LAYER_4, 19 on LAYER_5, 16 on LAYER_6, 10 on LAYER_7

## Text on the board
Board Geometry/Soldermask Bottom: 1 | 2 | M | 3 | 4
User.Comments: 05 | 02 | 03 | 04 | 06 | A | B | RELEASED FOR PROTOTYPE | RELEASED FOR PRODUCTION | 10/29/18 | 07/20/18 | 08/24/18 | 09/21/18 | 01/07/19 | 03/28/19 | 06/07/19 | M.DORUFF
Ref Des/Assembly Top: 3
Board Geometry/Soldermask Top: BRD3 | SR28C33741 B | 1 | BRD1 | 2 | M | 3 | 4 | BRD4 | CAD SIDE 1 | BRD2
DIMENSION: BRD3 | SR28C33741 B | 1 | BRD1 | 2 | M | 3 | 4 | BRD4 | CAD SIDE 1 | BRD2 | BURIED VIA | BLIND VIA | PER PANEL | DRILL QUANTITIES FOR SINGLE BOARD UNLESS NOTED | LAYER 2 AND 4 | LAYER 4 AND 6 | LAYER 6 AND 8 | LAYER 2 | MARK DETAILS A AND B | IN AREA INDICATED | 4PL
DISPLAY_TOP: 1 | 2 | M | 3 | 4
User.10: BD1 | BD2 | BD3 | BD4
User.18: 0.045mm | 0.05mm
User.25: FIGURE | SIZE | 1.500x0.600 | 1.800x0.500 | 1.900x1.500 | 2.000x0.800 | 3.200x1.600 | SLOT HOLES: TOP to BOTTOM | ALL UNITS ARE IN MILLIMETERS | PLATED | NON-PLATED | QTY | 2 | 1
User.29: FIGURE | SIZE | 0.075 | DRILL CHART: LAYER_7 to BOTTOM | ALL UNITS ARE IN MILLIMETERS | PLATED | QTY | 3425
User.30: FIGURE | SIZE | 0.075 | DRILL CHART: LAYER_6 to LAYER_7 | ALL UNITS ARE IN MILLIMETERS | PLATED | QTY | 3907
User.31: FIGURE | SIZE | 0.075 | DRILL CHART: LAYER_5 to LAYER_6 | ALL UNITS ARE IN MILLIMETERS | PLATED | QTY | 4129
User.32: FIGURE | SIZE | 0.075 | DRILL CHART: LAYER_4 to LAYER_5 | ALL UNITS ARE IN MILLIMETERS | PLATED | QTY | 4844
User.33: FIGURE | SIZE | 0.075 | DRILL CHART: LAYER_3 to LAYER_4 | ALL UNITS ARE IN MILLIMETERS | PLATED | QTY | 6614
User.34: FIGURE | SIZE | 0.075 | DRILL CHART: LAYER_2 to LAYER_3 | ALL UNITS ARE IN MILLIMETERS | PLATED | QTY | 7250
User.35: FIGURE | SIZE | 0.075 | DRILL CHART: TOP to LAYER_2 | ALL UNITS ARE IN MILLIMETERS | PLATED | QTY | 7384
User.37: FIGURE | SIZE | 2.200 | 0.350 | 1.000 | 1.200 | 1.500 | 1.600 | 2.000 | DRILL CHART: TOP to BOTTOM | ALL UNITS ARE IN MILLIMETERS | PLATED | NON-PLATED | QTY | 1 | 18 | 2 | 4
